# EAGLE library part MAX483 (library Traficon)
RS485 TRANSEIVER
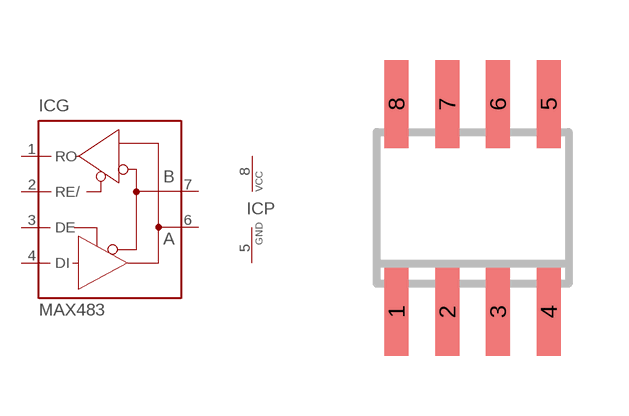
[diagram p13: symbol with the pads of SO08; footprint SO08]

Designator prefix IC; gates G=MAX481 P=VCC-GND

## MAX483CSA  [SO08]
1  G:RO  out
2  G:RE/  in
3  G:DE  in
4  G:DI  in
5  P:GND  pwr
6  G:A  pas
7  G:B  pas
8  P:VCC  pwr

## Footprint SO08 (pad centres in mm)
Small Outline Package
smd 0.6 x 2.2: 1 -1.905,-2.6; 2 -0.635,-2.6; 3 0.635,-2.6; 4 1.905,-2.6; 5 1.905,2.6; 6 0.635,2.6; 7 -0.635,2.6; 8 -1.905,2.6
